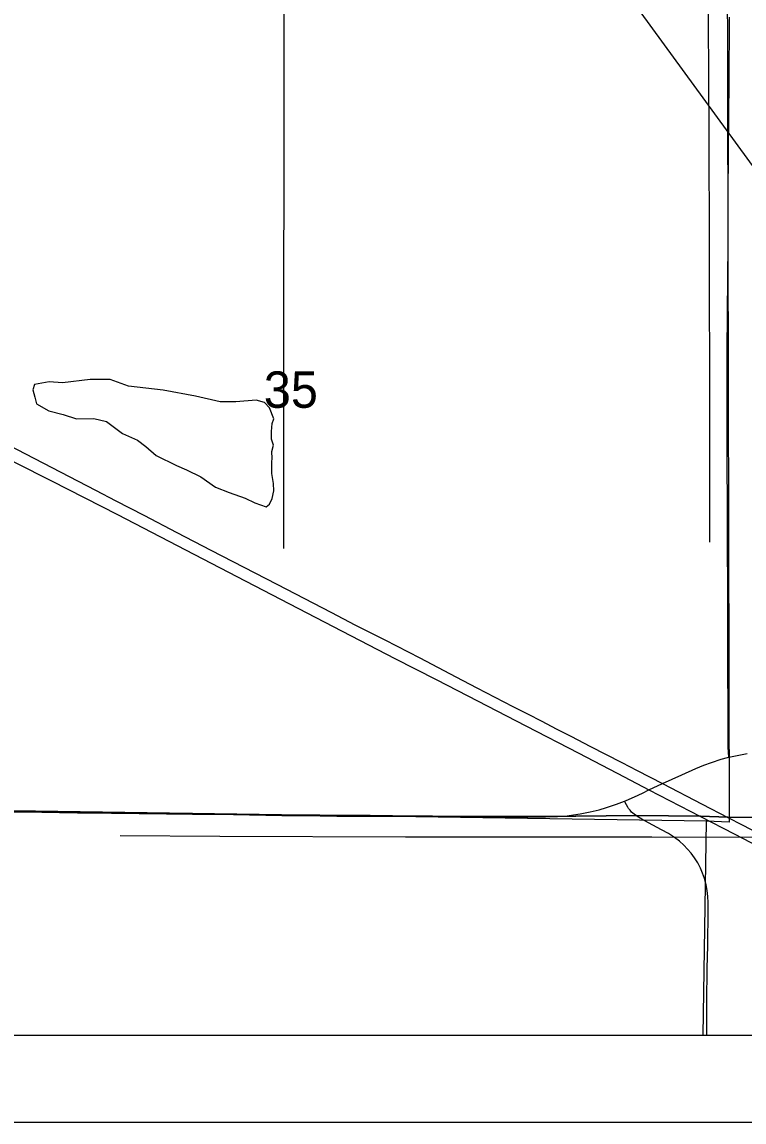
# Model space of a CAD drawing. Extents: x 0 to 34, y 0 to 22.
# Drawn here: x 2.893 to 3.723, y 14 to 15.265 of the extents above; entities that cross this region are included whole.
import ezdxf

# ---------------------------------------------------------------- set-up
doc = ezdxf.new("R2010")
doc.units = 0
for name, color, linetype in [('Default', 7, 'Continuous'), ('GM_X_Interstate_Route', 7, 'Continuous'), ('GM_X_Minor_Lake', 7, 'Continuous'), ('GM_X_Minor_River', 7, 'Continuous'), ('GM_X_Rail_Line', 7, 'Continuous'), ('GM_X_Section', 7, 'Continuous'), ('GM_X_Section_Text', 7, 'Continuous'), ('GM_X_State_Route', 7, 'Continuous'), ('GM_X_Township_Road', 7, 'Continuous'), ('SH_Data', 7, 'Continuous')]:
    doc.layers.add(name, color=color, linetype=linetype)

msp = doc.modelspace()

# ---------------------------------------------------------------- linework, layer by layer
at = {"layer": 'Default'}
msp.add_lwpolyline([(2.662, 14.1), (3.676, 14.1), (3.6799, 14.3459), (2.7019, 14.3602), (2.6651, 14.3602)], close=True, dxfattribs=at)
at = {"layer": 'GM_X_Interstate_Route'}
for points in [[(2.7808, 14.8135), (2.8655, 14.7685), (2.8848, 14.7582), (2.9264, 14.7371), (3.0022, 14.6983), (3.1397, 14.6271), (3.2203, 14.5854), (3.3213, 14.533), (3.3689, 14.5086), (3.4054, 14.4898), (3.4722, 14.4553), (3.533, 14.4239), (3.5854, 14.3967), (3.6138, 14.3818)], [(2.8459, 14.794), (2.9769, 14.7265), (3.0006, 14.7142), (3.0325, 14.6975), (3.0705, 14.6775), (3.1097, 14.6572), (3.1855, 14.6183), (3.2484, 14.5857), (3.2755, 14.5716), (3.3098, 14.5541), (3.3502, 14.5334), (3.3915, 14.5118), (3.4158, 14.4992), (3.4572, 14.4778), (3.4749, 14.4687), (3.4898, 14.461), (3.508, 14.4516), (3.5246, 14.443), (3.5456, 14.4322), (3.5827, 14.4132), (3.6004, 14.4041), (3.6294, 14.389), (3.6749, 14.3655), (3.7047, 14.35), (3.7212, 14.3415), (3.7505, 14.3263)], [(3.6138, 14.3818), (3.6731, 14.3512), (3.7118, 14.3312), (3.7687, 14.3019), (3.8141, 14.2788), (3.8392, 14.2663), (3.8655, 14.2537), (3.8898, 14.2426), (3.9216, 14.2285), (3.9565, 14.2137), (3.9858, 14.2016), (4.0124, 14.1912), (4.0409, 14.1806), (4.0801, 14.1666), (4.1077, 14.1571), (4.1343, 14.1485), (4.1646, 14.1393), (4.1956, 14.1303), (4.2292, 14.1211), (4.264, 14.1121), (4.2948, 14.1046), (4.3145, 14.1)], [(2.8691, 14.3573), (2.8946, 14.3569), (2.9561, 14.3559), (2.9953, 14.3556), (3.0587, 14.355), (3.0885, 14.3546), (3.1078, 14.3543), (3.1358, 14.3539), (3.1911, 14.353), (3.2353, 14.3526), (3.2545, 14.3523), (3.2891, 14.3522), (3.2931, 14.3522), (3.3186, 14.3521), (3.3646, 14.3516), (3.4, 14.351), (3.474, 14.351), (3.4946, 14.3512), (3.5996, 14.3523), (3.6729, 14.3517), (3.7044, 14.3506), (4.0237, 14.3492)], [(4.0237, 14.3492), (3.7044, 14.3506), (3.6729, 14.3517), (3.5996, 14.3523), (3.4946, 14.3512), (3.474, 14.351), (3.4, 14.351), (3.3646, 14.3516), (3.3186, 14.3521), (3.2931, 14.3522), (3.2891, 14.3522), (3.2545, 14.3523), (3.2353, 14.3526), (3.1911, 14.353), (3.1358, 14.3539), (3.1078, 14.3543), (3.0885, 14.3546), (3.0587, 14.355), (2.9953, 14.3556), (2.9561, 14.3559), (2.8946, 14.3569), (2.8691, 14.3573)], [(2.1, 14.1), (4.7021, 14.1)]]:
    msp.add_lwpolyline(points, dxfattribs=at)
at = {"layer": 'GM_X_Minor_Lake'}
msp.add_line((3.1803, 14.7627), (3.18, 14.7706), dxfattribs=at)
msp.add_lwpolyline([(3.18, 14.7706), (3.1819, 14.7782), (3.1797, 14.785), (3.1794, 14.7937), (3.1802, 14.8028), (3.1821, 14.8085), (3.1773, 14.8211), (3.1716, 14.8272), (3.1618, 14.8299), (3.1384, 14.8278), (3.1206, 14.8279), (3.0923, 14.8345), (3.0549, 14.8412), (3.0152, 14.846), (2.9941, 14.8534), (2.971, 14.8535), (2.9392, 14.8499), (2.9237, 14.8508), (2.907, 14.8479), (2.9051, 14.8418), (2.9073, 14.8334), (2.9092, 14.8255), (2.9235, 14.8174), (2.9397, 14.8135), (2.9552, 14.8085), (2.9752, 14.8087), (2.9896, 14.8052), (3.008, 14.7914), (3.0254, 14.7837), (3.0348, 14.7765), (3.0468, 14.7661), (3.0702, 14.7546), (3.0819, 14.7496), (3.0984, 14.7415), (3.115, 14.7297), (3.1309, 14.7235), (3.1493, 14.7173), (3.1603, 14.7119), (3.1735, 14.7073), (3.1773, 14.7103), (3.1803, 14.7167), (3.1823, 14.7254), (3.182, 14.7338), (3.1798, 14.7455), (3.1799, 14.7588), (3.1803, 14.7627)], dxfattribs=at)
at = {"layer": 'GM_X_Minor_River'}
for points in [[(3.6785, 17.0216), (3.6816, 16.7654), (3.6827, 16.5423), (3.6841, 16.3464), (3.6825, 16.1017), (3.6821, 15.8805), (3.6804, 15.6582), (3.6808, 15.4396), (3.6814, 15.3334), (3.6828, 15.1345), (3.683, 15.0055), (3.6833, 14.8112), (3.6833, 14.6667)], [(3.1937, 14.6594), (3.1937, 14.9), (3.1943, 15.1508), (3.1942, 15.339), (3.1938, 15.6247), (3.1921, 15.8008), (3.1928, 16.0148), (3.1938, 16.2242), (3.194, 16.3798), (3.1923, 16.6356), (3.1907, 16.6743), (3.1894, 16.725)], [(4.6797, 14.3307), (4.4822, 14.3293), (4.2586, 14.3284), (4.0313, 14.3272), (3.8387, 14.3269), (3.617, 14.3274), (3.3337, 14.3274), (3.12, 14.3282), (3.0054, 14.329)]]:
    msp.add_lwpolyline(points, dxfattribs=at)
at = {"layer": 'GM_X_Rail_Line'}
msp.add_lwpolyline([(4.4636, 14.1), (4.2829, 14.3475), (4.0202, 14.7061), (3.9178, 14.8467), (3.7641, 15.0572), (3.5439, 15.3588), (3.2112, 15.8143), (3.0989, 15.9678), (2.9869, 16.1219), (2.8009, 16.3767), (2.7485, 16.4478), (2.7239, 16.4783), (2.6984, 16.5122), (2.4472, 16.8567), (2.3237, 17.0297), (2.1, 17.3362)], dxfattribs=at)
at = {"layer": 'GM_X_Section'}
msp.add_lwpolyline([(3.7036, 15.3519), (3.7061, 14.3445), (3.6799, 14.3459), (2.7019, 14.3602), (2.7001, 15.3638)], close=True, dxfattribs=at)
at = {"layer": 'GM_X_State_Route'}
for points in [[(3.5857, 14.3689), (3.5876, 14.3697), (3.5973, 14.3738), (3.6063, 14.378), (3.6138, 14.3818), (3.6294, 14.389), (3.6515, 14.3991), (3.6679, 14.4065), (3.6771, 14.4103), (3.6858, 14.4134), (3.697, 14.417), (3.7042, 14.419), (3.7056, 14.4193)], [(3.7056, 14.4193), (3.7151, 14.4214), (3.7266, 14.4237)], [(3.4513, 14.3505), (3.4743, 14.3505), (3.4948, 14.3507), (3.5085, 14.3512), (3.5197, 14.3521), (3.5271, 14.353), (3.5345, 14.3542), (3.5461, 14.3566), (3.5565, 14.359), (3.5648, 14.3615), (3.5765, 14.3655), (3.5857, 14.3689)], [(2.7055, 14.359), (2.7232, 14.359), (2.7903, 14.358), (2.8357, 14.3574), (2.8693, 14.3567), (2.8948, 14.3564), (2.9563, 14.3554), (2.9955, 14.355), (3.0589, 14.3544), (3.0888, 14.354), (3.108, 14.3538), (3.136, 14.3533), (3.1913, 14.3525), (3.2355, 14.3521), (3.2548, 14.3517), (3.2893, 14.3516), (3.2933, 14.3516), (3.3188, 14.3516), (3.3648, 14.3511), (3.4002, 14.3504), (3.4513, 14.3505)]]:
    msp.add_lwpolyline(points, dxfattribs=at)
at = {"layer": 'GM_X_Township_Road'}
for points in [[(3.7056, 14.4193), (3.7051, 14.4307), (3.7049, 14.4368), (3.7048, 14.4822), (3.7047, 14.5139), (3.7045, 14.5686), (3.7045, 14.6031), (3.7042, 14.6727), (3.7041, 14.7194), (3.7039, 14.7467), (3.7038, 14.802), (3.7038, 14.8549), (3.7038, 14.8735), (3.7038, 14.8841), (3.704, 14.9314), (3.7045, 14.9687), (3.7048, 15.0103), (3.7051, 15.07), (3.7052, 15.1104), (3.7052, 15.1197), (3.7053, 15.1265), (3.7053, 15.1309), (3.7055, 15.1396), (3.7056, 15.1452), (3.7058, 15.1601), (3.7061, 15.1936), (3.7063, 15.2701)], [(3.5857, 14.3689), (3.5876, 14.3697), (3.5973, 14.3738), (3.6063, 14.378), (3.6138, 14.3818), (3.6294, 14.389), (3.6515, 14.3991), (3.6679, 14.4065), (3.6771, 14.4103), (3.6858, 14.4134), (3.697, 14.417), (3.7042, 14.419), (3.7056, 14.4193)], [(3.6803, 14.1), (3.6804, 14.1197), (3.6805, 14.1458), (3.6808, 14.1688), (3.6808, 14.1794), (3.681, 14.1868), (3.6814, 14.2054), (3.6821, 14.2401), (3.6821, 14.2525), (3.6817, 14.2593), (3.6808, 14.266), (3.6795, 14.2727), (3.6776, 14.2798), (3.6755, 14.2862), (3.6731, 14.2919), (3.6699, 14.2979), (3.6663, 14.3036), (3.6623, 14.309), (3.6583, 14.3137), (3.654, 14.3182), (3.649, 14.3227), (3.6431, 14.3271), (3.6364, 14.3315), (3.6283, 14.336), (3.6134, 14.3438), (3.6057, 14.348), (3.5999, 14.3517), (3.5968, 14.3539), (3.5938, 14.3562), (3.592, 14.3583), (3.5903, 14.3605), (3.5894, 14.3621), (3.588, 14.3647), (3.5857, 14.3689)]]:
    msp.add_lwpolyline(points, dxfattribs=at)
at = {"layer": 'SH_Data'}
for p, q in [((2.1, 14.1), (8.9, 14.1)), ((2, 14), (9, 14))]:
    msp.add_line(p, q, dxfattribs=at)

# ---------------------------------------------------------------- texts
at = {"layer": 'GM_X_Section_Text'}
msp.add_text('35', height=0.04186, rotation=0, dxfattribs=at).set_placement((3.1707, 14.821))

doc.saveas('drawing.dxf')
